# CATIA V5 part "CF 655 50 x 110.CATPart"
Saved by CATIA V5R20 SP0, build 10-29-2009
Part number: CF 655 50 x 110
Definition: NONE
Nomenclature: CF 655 50 x 110
Source: Unknown
Description: CF 655 50 x 110
Bounding box of the stored display mesh (mm): x -75 to 35, y -39.5 to 39.5, z -39.5 to 39.5
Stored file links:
  C:\Users\Utente\Desktop\IO LAVORO\3D X SITO CF\X SITO\CF 655\CF 655 50 x 110.CATPart
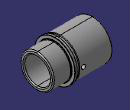
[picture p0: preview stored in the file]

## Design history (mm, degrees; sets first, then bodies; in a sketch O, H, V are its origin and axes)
Body1 "CF 655 50 x 110" (main body)
  Solid1: solid without history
